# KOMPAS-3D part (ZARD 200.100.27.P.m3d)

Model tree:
1. Поверхность без истории:1
2. Поверхность без истории:2
3. Поверхность без истории:3
4. Поверхность без истории:4
5. Поверхность без истории:5
6. Поверхность без истории:6
7. Поверхность без истории:7
8. Поверхность без истории:8
9. Поверхность без истории:9
10. Поверхность без истории:10
11. Поверхность без истории:11
12. Поверхность без истории:12
13. Поверхность без истории:13
14. Поверхность без истории:14
15. Поверхность без истории:15
16. Поверхность без истории:16
17. Поверхность без истории:17
18. Поверхность без истории:18
19. Поверхность без истории:19
20. Поверхность без истории:20
21. Поверхность без истории:21
22. Поверхность без истории:22
23. Поверхность без истории:23
24. Поверхность без истории:24
25. Поверхность без истории:25
26. Поверхность без истории:26
27. Поверхность без истории:27
28. Поверхность без истории:28
29. Поверхность без истории:29
30. Поверхность без истории:30
31. Поверхность без истории:31
32. Поверхность без истории:32
33. Поверхность без истории:33
34. Поверхность без истории:34
35. Поверхность без истории:35
36. Поверхность без истории:36
37. Поверхность без истории:37
38. Поверхность без истории:38
39. Поверхность без истории:39
40. Поверхность без истории:40
41. Поверхность без истории:41
42. Поверхность без истории:42
43. Поверхность без истории:43
44. Поверхность без истории:44
45. Поверхность без истории:45
46. Поверхность без истории:46
47. Поверхность без истории:47
48. Поверхность без истории:48
49. Поверхность без истории:49
50. Поверхность без истории:50
51. Поверхность без истории:51
52. Поверхность без истории:52
53. Поверхность без истории:53
54. Поверхность без истории:54
55. Поверхность без истории:55
56. Поверхность без истории:56
57. Поверхность без истории:57
58. Поверхность без истории:58
59. Поверхность без истории:59
60. Поверхность без истории:60
61. Поверхность без истории:61
62. Поверхность без истории:62
63. Поверхность без истории:63
64. Поверхность без истории:64
65. Поверхность без истории:65
66. Поверхность без истории:66
67. Поверхность без истории:67
68. Поверхность без истории:68
69. Поверхность без истории:69
70. Поверхность без истории:70
71. Поверхность без истории:71
72. Поверхность без истории:72
73. Поверхность без истории:73
74. Поверхность без истории:74
75. Поверхность без истории:75
76. Поверхность без истории:76
77. Поверхность без истории:77
78. Поверхность без истории:78
79. Поверхность без истории:79
80. Поверхность без истории:80
81. Поверхность без истории:81
82. Поверхность без истории:82
83. Поверхность без истории:83
84. Поверхность без истории:84
85. Поверхность без истории:85
86. Поверхность без истории:86
87. Поверхность без истории:87
88. Поверхность без истории:88
89. Поверхность без истории:89
90. Поверхность без истории:90
91. Поверхность без истории:91
92. Поверхность без истории:92
93. Поверхность без истории:93
94. Поверхность без истории:94
95. Поверхность без истории:95
96. Поверхность без истории:96
97. Поверхность без истории:97
98. Поверхность без истории:98
99. Поверхность без истории:99
100. Поверхность без истории:100
101. Поверхность без истории:101
102. Поверхность без истории:102
103. Поверхность без истории:103
104. Поверхность без истории:104
105. Поверхность без истории:105
106. Поверхность без истории:106

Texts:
  ЗАРД 200.100.27-ХХ.Р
